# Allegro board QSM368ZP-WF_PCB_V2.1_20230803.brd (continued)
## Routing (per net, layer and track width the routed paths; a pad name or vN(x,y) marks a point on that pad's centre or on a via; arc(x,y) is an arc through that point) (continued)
HDMITX_SCL_M: length 9.3
  TOP w0.1: v1(7.2,12.43) J0401.15
  BOTTOM w0.1: U0413.3 10.18,15.8 9.53,15.15 8.2,15.15 7.2,14.15 v1(7.2,12.43)
HDMITX_SDA: length 170.4
  TOP w0.1: v1(12.45,6.92) 12.65,6.72 25.95,6.72 26.23,6.45 28.1,6.45 29.7,4.85 29.7,4.38 30.02,4.05 v1(30.82,4.05) ; U1301.385 v1(67.5,66.67)
  INNER LAYER 2 w0.1: v1(91.34,33.74) 91.5,33.58 91.5,32.65 91.45,32.6 91.45,25.88 91.1,25.52 v1(90.45,25.52)
  INNER LAYER 3 w0.1: v1(8.22,21.05) 8.22,20.02 9.15,19.1 11.2,19.1 11.7,18.6 11.7,7.67 v1(12.45,6.92) ; v1(67.5,66.67) 67.61,66.67 67.92,66.36 67.92,64.15 72.01,60.07 74.37,60.07 77.95,56.49 77.95,47 91.21,33.74 v1(91.34,33.74) ; v1(90.45,25.52) 89.88,25.52 81.58,17.23 81.58,5.26 80.17,3.85 60,3.85 57.7,1.55 42.15,1.55 39.9,3.8 31.07,3.8 v1(30.82,4.05)
  BOTTOM w0.1: U0405.2 7.61,20.62 7.6,20.62 R0417.1 v1(8.22,21.05)
HDMITX_SDA_M: length 7.4
  TOP w0.1: J0401.16 6.7,12.32 v1(6.6,12.43)
  BOTTOM w0.1: v1(6.6,12.43) 6.7,12.53 6.7,15.7 6.65,15.75 D0406.1 R0420.1 U0405.3
HP_SNS: length 65.6
  TOP w0.25: U1301.101 v1(29.35,70.58) ; R1018.1 v1(23.57,15.22)
  INNER LAYER 3 w0.25: v1(23.57,15.22) 23.57,15.6 23.15,16.02 23.15,32.17 24.05,33.08 24.05,41.88 21.05,44.88 21.05,48.25 22.6,49.8 26.23,49.8 28.4,51.97 28.4,69.62 v1(29.35,70.58)
HPL_OUT: length 95
  TOP w0.25: v1(29.05,13.02) 29.79,12.28 29.79,10.61 29.77,10.6 R1023.1 ; v1(12.72,74.85) 12.72,75.03 13.5,75.8 28.12,75.8 30.15,73.78 U1301.100 30.15,72.58 v1(30,72.42)
  INNER LAYER 3 w0.25: v1(29.05,13.02) 28.89,13.02 23.52,18.38 23.52,32.02 24.45,32.95 24.45,41.98 21.4,45.03 21.4,48.08 22.77,49.45 26.38,49.45 28.75,51.82 28.75,69.3 30.15,70.7 30.15,72.28 v1(30,72.42)
  BOTTOM w0.25: v1(12.72,74.85) 12.35,74.47 R1004.2 C1017.1
HPR_OUT: length 84.8
  TOP w0.25: v1(28.55,72.42) U1301.102 28.55,74.4 27.73,75.22 13.93,75.22 v1(13.57,74.88) ; v1(22.76,15.69) 21.77,14.7 R1010.1
  INNER LAYER 3 w0.25: v1(28.55,72.42) 28.55,71.9 28.02,71.38 28.02,52.12 26.08,50.17 22.45,50.17 20.68,48.4 20.68,44.73 23.65,41.75 23.65,33.17 22.77,32.3 22.77,15.7 v1(22.76,15.69)
  BOTTOM w0.25: 14.22,74.28 14.22,75.12 13.82,75.12 v1(13.57,74.88)
I2C1_SCL_TP: length 141.2
  TOP w0.1: v1(53.17,92.17) 53.17,92.03 52.73,91.58 48.1,91.58 47.4,90.88 44.8,90.88 v1(44.27,90.35) 43.24,90.35 42.35,91.24 42.35,91.25 41.05,92.55 R0517.1 39.83,92.97 39.77,93.03 D0504.2 39.77,94.22 40.6,95.05 J0503.2 ; J1201.17 114.62,84.8 113.17,83.35 111.1,83.35 110.95,83.2 102.78,83.2 100.21,85.78 96,85.78 95.85,85.62 95.85,85.38 v1(95.42,84.95) ; U1301.45 v1(47.75,66.53)
  INNER LAYER 3 w0.1: v1(95.42,84.95) 94.6,84.12 79.85,84.12 78.1,82.38 74.3,82.38 70.47,86.2 70.47,95.03 67.98,97.53 54.88,97.53 53.73,96.38 53.73,93.12 53.17,92.58 v1(53.17,92.17) ; v1(44.27,90.35) 44.85,90.35 45,90.2 45,89.35 47.6,86.75 47.6,76.85 49.85,74.6 54.5,74.6 57.6,71.5 57.6,68.37 56.5,67.28 49.42,67.28 48.67,66.53 v1(47.75,66.53)
I2C1_SDA_TP: length 145.8
  TOP w0.1: v1(54.7,95.75) 54.7,95.12 55.23,94.6 55.23,93.47 55.15,93.4 55.15,93 54.73,92.58 54.35,92.58 54.15,92.38 54.15,92.15 54.02,92.03 54.02,90.85 52.9,89.72 45.6,89.72 v1(45.4,89.53) 45.25,89.38 43.12,89.38 42,90.5 39.3,90.5 38.45,91.35 38.45,92.3 38.7,92.55 R0508.1 38.98,93.05 39.08,93.15 D0509.2 39.08,93.95 40.1,94.97 J0503.1 ; J1201.19 114.3,87.25 109.62,87.25 109.2,87.67 94.22,87.67 94,87.45 94,83.15 v1(93.5,82.65) ; v1(49.35,66.53) U1301.40
  INNER LAYER 3 w0.1: v1(93.5,82.65) 93.25,82.4 89.08,82.4 88.05,83.42 80.14,83.42 78.39,81.67 73.95,81.67 69.67,85.95 69.67,94.78 67.65,96.8 65.15,96.8 64.5,96.15 63.73,96.15 63.08,96.8 56.05,96.8 55,95.75 v1(54.7,95.75) ; v1(49.35,66.53) 49.35,66.9 49.52,67.08 56.6,67.08 57.8,68.28 57.8,71.6 54.6,74.8 49.95,74.8 47.8,76.95 47.8,86.85 45.4,89.25 v1(45.4,89.53)
I2C2_SCL_M1: length 104.4
  TOP w0.1: J0201.13 93.85,97 v1(93.95,96.9) ; U1301.287 58.95,37.17 58.55,37.58 v1(58.55,37.73) ; v1(96.7,80.45) 96.2,79.95 96.2,71.87 95.42,71.1 95.42,63.88 82.6,51.05 74.35,51.05 73.85,50.55 73.15,50.55 72.95,50.35 v1(72.95,50.02)
  INNER LAYER 3 w0.1: v1(72.95,50.02) 72.78,49.85 72.08,49.85 71.28,49.05 70.42,49.05 69.78,48.4 65.42,48.4 63.06,46.04 63.06,44.64 58.6,40.17 58.6,37.77 v1(58.55,37.73) ; v1(93.95,96.9) 93.95,96.45 93.62,96.12 90.28,96.12 89.95,95.8 89.95,95.22 91.35,93.83 92.97,93.83 94.97,91.83 94.97,90.8 98.78,87 98.78,82.18 96.94,80.34 96.8,80.34 v1(96.7,80.45)
  BOTTOM w0.1: v1(93.95,96.9) 94.17,96.9 94.53,96.55 94.53,95.1 93.92,94.5 89.62,94.5 89.42,94.7 88.25,94.7 88.12,94.83 R0207.1
I2C2_SDA_M1: length 101.3
  TOP w0.1: v1(94.12,96.05) 94.15,96.03 J0201.12 ; U1301.284 58.15,38.75 57.62,39.27 v1(57.62,39.45) ; v1(73.58,50.15) 73.75,50.15 74.45,50.85 82.7,50.85 95.62,63.77 95.62,70.92 96.42,71.72 96.42,79.55 v1(96.69,79.81)
  INNER LAYER 3 w0.1: v1(73.58,50.15) 73.47,50.15 72.65,50.98 71.75,50.98 71.38,50.6 71.38,50.27 70.75,49.65 70.12,49.65 69.47,49 65.08,49 62.42,46.35 62.42,44.85 57.88,40.3 57.88,39.7 v1(57.62,39.45) ; v1(94.12,96.05) 94,95.92 90.38,95.92 90.15,95.7 90.15,95.33 91.45,94.03 93.15,94.03 95.25,91.92 95.25,90.83 98.97,87.1 98.97,82.05 96.92,80 96.87,80 v1(96.69,79.81)
  BOTTOM w0.1: v1(94.12,96.05) 94.33,95.85 94.33,95.2 93.83,94.7 89.72,94.7 89.3,95.12 R0221.1
I2C3_SCL_M0: length 122.8
  TOP w0.1: J0202.13 83.17,97.15 v1(83.72,96.6) ; U1301.273 v1(54.15,37.55) ; v1(72.53,50.48) 72.83,50.77 73.78,50.77 74.25,51.25 82.5,51.25 95.2,63.95 95.2,71.28 95.9,71.97 95.9,81.97 97.15,83.22 97.15,84.25 v1(97.4,84.5) 97.53,84.62 99.58,84.62 103.47,80.72 109.53,80.72 110.47,81.67 113.88,81.67 J1201.13
  INNER LAYER 3 w0.1: v1(97.4,84.5) 96.47,85.42 96.47,87.45 89.58,94.35 85.45,94.35 84.25,95.55 83.83,95.55 83.7,95.67 83.7,96.58 v1(83.72,96.6) ; v1(72.53,50.48) 72.15,50.1 71.97,50.1 71.12,49.25 70.33,49.25 69.67,48.6 65.3,48.6 62.85,46.15 62.85,44.71 58.4,40.26 58.4,39.27 57.6,38.48 54.85,38.48 54.15,37.77 v1(54.15,37.55)
  BOTTOM w0.1: v1(83.72,96.6) 83.72,97.38 84.33,97.97 87.65,97.97 87.85,97.78 R0208.1
I2C3_SDA_M0: length 129.8
  TOP w0.1: U1301.268 v1(52.55,37.48) ; J1201.11 115.62,79.92 115.62,81.28 115.03,81.88 110.39,81.88 109.44,80.92 103.56,80.92 99.58,84.9 96.9,84.9 96.72,84.72 v1(96.72,84.58) 96.92,84.38 96.92,83.43 95.67,82.18 95.67,72.12 95,71.45 95,64.05 82.42,51.48 74.18,51.48 73.7,51 72.38,51 v1(71.9,50.52) ; J0202.12 83.47,95.33 83.3,95.5 v1(83.3,96)
  INNER LAYER 3 w0.1: v1(71.9,50.52) 71.9,50.48 70.88,49.45 70.22,49.45 69.58,48.8 65.2,48.8 62.63,46.23 62.63,44.77 58.2,40.34 58.2,39.38 57.51,38.69 54.71,38.69 53.5,37.48 v1(52.55,37.48) ; v1(83.3,96) 83.3,95.78 83.72,95.35 84.15,95.35 85.35,94.15 89.47,94.15 96.28,87.35 96.28,85.33 96.72,84.88 v1(96.72,84.58)
  BOTTOM w0.1: v1(83.3,96) 83.33,96.03 83.33,97.28 84.25,98.2 88.85,98.2 88.97,98.08 R0222.1
I2C4_SCL_M1: length 141.8
  TOP w0.1: U1301.159 v1(30.52,49.88) ; v1(36.75,98.55) 36.75,97.47 37.8,96.42 v1(37.8,90.85) ; v1(90.2,86.85) 90,86.65 90,84.95 91,83.95 91,75.97 87.38,72.35 v1(87.38,71.97)
  INNER LAYER 3 w0.1: v1(30.52,49.88) 30.52,50.1 31.02,50.6 31.02,56 31.57,56.55 31.57,69.77 33.33,71.53 36.4,71.53 39.52,74.65 39.52,87.3 37.8,89.03 v1(37.8,90.85) ; v1(90.2,86.85) 90.1,86.95 85.78,86.95 83.05,89.67 72.3,89.67 71.72,90.25 71.72,95.38 68.47,98.62 53.42,98.62 53.15,98.35 v1(53,98.35) 52.48,98.35 51.95,97.83 48.02,97.83 47.6,97.4 45.48,97.4 45.05,97.83 42.48,97.83 42.17,98.12 37.17,98.12 v1(36.75,98.55)
  BOTTOM w0.1: v1(87.38,71.97) 87.17,71.78 R1206.1 87.03,71.38 86.55,70.9 U1204.2 ; v1(53,98.35) 53,97.05 52.73,96.78 R0430.2 52.73,94.03 U0410.2
I2C4_SDA_M1: length 143.8
  TOP w0.1: v1(38.2,90.4) 38.2,91.05 38.02,91.22 38.02,96.5 36.95,97.58 36.95,98.08 v1(37.4,98.53) ; v1(90.83,86.88) 90.25,86.3 90.25,85 91.22,84.03 91.22,75.85 88.3,72.92 88.3,71 v1(87.17,69.88) ; U1301.155 v1(31.55,51.4)
  INNER LAYER 3 w0.1: v1(31.55,51.4) 31.23,51.73 31.23,55.88 31.8,56.45 31.8,69.67 33.42,71.3 36.48,71.3 39.73,74.55 39.73,87.4 38.2,88.92 v1(38.2,90.4) ; v1(37.4,98.53) 37.6,98.33 42.27,98.33 42.58,98.03 45.15,98.03 45.58,97.6 47.5,97.6 47.92,98.03 51.58,98.03 v1(51.8,98.25) 52.08,98.25 52.38,98.55 52.62,98.55 52.92,98.85 68.55,98.85 71.92,95.48 71.92,90.35 72.4,89.88 83.14,89.88 85.76,87.25 90.45,87.25 v1(90.83,86.88)
  BOTTOM w0.1: U1204.3 86.6,70.2 86.92,70.53 R1203.1 v1(87.17,69.88) ; v1(51.8,98.25) 51.55,98.5 R0424.2 50.95,97.35 51.12,97.17 51.12,96.75 49.5,95.12 U0407.2
I2S3_LRCKM1: length 77.8
  TOP w0.1: U1301.388 69,69.08 70.55,70.62 77.2,70.62 v1(78.1,69.72) ; v1(94.12,32.17) 94.22,32.17 97.1,29.3 106.12,29.3 106.62,28.8 106.62,25.27 106.15,24.8 105.88,24.8 R0714.1
  INNER LAYER 3 w0.1: v1(78.1,69.72) 78.1,69.22 78.53,68.8 78.53,63.6 77.47,62.55 77.47,59.38 79.6,57.25 79.6,47.75 91.15,36.2 92.92,36.2 94.7,34.42 94.7,32.75 v1(94.12,32.17)
I2S3_SCLKM1: length 80.8
  TOP w0.1: U1301.386 69.22,67.47 71.67,69.92 v1(76.58,69.92) ; R0724.1 103.17,24.57 103.28,24.48 104.15,24.48 104.53,24.1 106.53,24.1 107.28,24.85 107.28,29.12 106.5,29.9 97.72,29.9 94.05,33.58 94.05,33.8 v1(94.03,33.83)
  INNER LAYER 3 w0.1: v1(94.03,33.83) 94.03,34.38 92.6,35.8 90.95,35.8 79.17,47.58 79.17,57.08 77.05,59.2 77.05,62.8 77.94,63.69 77.94,68.56 v1(76.58,69.92)
I2S3_SDIM1: length 79.7
  TOP w0.1: U1301.383 68.92,65.88 69.25,66.2 69.25,67.15 71.83,69.72 75.17,69.72 v1(76.25,68.65) ; R0703.1 104.03,24.9 104.62,24.3 106.4,24.3 107.03,24.93 107.03,29.05 106.38,29.7 97.55,29.7 93.83,33.42 v1(93.33,33.42)
  INNER LAYER 3 w0.1: v1(93.33,33.42) 93.17,33.42 92.88,33.73 92.88,34.58 92.12,35.33 90.83,35.33 78.75,47.4 78.75,56.9 76.12,59.52 76.12,63.42 77.28,64.58 77.28,67.62 v1(76.25,68.65)
I2S3_SDOM1: length 67.8
  TOP w0.1: R0710.1 104.88,24.8 105.17,24.5 106.28,24.5 106.83,25.05 106.83,28.93 106.25,29.5 97.38,29.5 93.92,32.95 v1(93.72,32.95) ; v1(69.28,64.28) U1301.380
  INNER LAYER 3 w0.1: v1(93.72,32.95) 93.15,32.95 92.62,33.48 92.62,34.52 92.03,35.12 90.72,35.12 78.55,47.3 78.55,56.77 74.55,60.77 72.33,60.77 69.28,63.83 v1(69.28,64.28)
INTB_A: length 9.5
  BOTTOM w0.1: R0953.2 111.72,50.8 R0935.2 D0902.1 111.25,48.6 110.62,47.98 109.38,47.98 109.03,47.62 109.03,46.73 107.62,45.33 U0902.31
LAN0_D2_REC1_A: length 1.6
  BOTTOM w0.3: R0911.2 98.92,24.23 U0901.24
LAN0_D2_REC2_A: length 1.6
  BOTTOM w0.3: U0901.21 101.92,24.27 R0918.2
LAN0_D7_REC1_A: length 1.6
  BOTTOM w0.3: U0901.15 107.92,24.25 R0924.2
LAN0_D7_REC2_A: length 1.6
  BOTTOM w0.3: R0943.2 104.92,24.29 U0901.18
LCD0_BL_PWM4: length 80.3
  TOP w0.1: U0409.5 R0422.2 v1(69.28,89.62) ; v1(48.15,88.05) 49.62,89.53 53,89.53 54.23,90.75 54.23,91.85 v1(54.55,92.17) ; U1301.55 v1(44.55,66.55)
  INNER LAYER 3 w0.1: v1(54.55,92.17) 54.55,92.58 54.85,92.88 54.85,93.62 54.42,94.05 54.42,94.85 56.17,96.6 62.98,96.6 63.62,95.95 64.6,95.95 65.25,96.6 67.55,96.6 69.47,94.67 69.47,89.83 v1(69.28,89.62) ; v1(48.15,88.05) 48.4,87.8 48.4,77.2 50.2,75.4 54.85,75.4 58.4,71.85 58.4,68.03 56.85,66.47 54.52,66.47 52.35,64.3 46.45,64.3 44.55,66.2 v1(44.55,66.55)
LCD1_BL_PWM5: length 14
  TOP w0.1: U1301.25 v1(54.15,64.72)
  INNER LAYER 2 w0.1: v1(54.15,64.72) 55.27,65.85 57.77,65.85 59.73,67.8 62.38,67.8 v1(63.58,69)
  BOTTOM w0.1: U0504.5 62.58,69.22 R0512.2 v1(63.58,69)
LCD_RST_L_GPIO3_C7: length 146.1
  TOP w0.1: U1301.322 67.42,46.05 67.42,46.65 67.53,46.75 68.88,46.75 69.25,47.12 69.25,47.82 70.6,49.17 83.78,49.17 90.09,55.49 90.09,57.94 95.83,63.67 95.83,70.75 97.4,72.33 97.4,81.15 v1(97.08,81.47) ; v1(29.48,98.53) J0501.6 ; v1(54.15,93.28) 53.98,93.1 53.4,93.1 52.98,93.53 52.67,93.53 51.65,92.5 45.4,92.5 v1(45.2,92.7)
  INNER LAYER 3 w0.1: v1(29.48,98.53) 29.75,98.53 30.35,97.92 30.57,97.92 30.98,97.53 34.98,97.53 35.95,96.55 40.88,96.55 44.52,92.9 45,92.9 v1(45.2,92.7) ; v1(97.08,81.47) 96.78,81.78 95.88,81.78 93.72,83.92 79.93,83.92 78.18,82.17 74.2,82.17 70.25,86.12 70.25,94.95 67.9,97.3 54.95,97.3 53.92,96.28 53.92,93.5 v1(54.15,93.28)
LCDC_D0: length 61.1
  TOP w0.1: U1301.366 68.65,58.67 71.9,61.92 74.9,61.92 79.67,66.7 83.5,66.7 85.76,68.96 88.76,68.96 92.18,72.38 92.18,84.25 92.3,84.38 92.3,85.9 v1(92.15,86.05)
  INNER LAYER 3 w0.1: v1(79.5,88.75) 80.2,88.75 83.6,85.35 91.03,85.35 91.72,86.05 v1(92.15,86.05)
  BOTTOM w0.1: v1(79.5,88.75) 79.6,88.65 79.6,87.75 80.15,87.2 R0203.2 80.62,88.2 U0202.3
LCDC_D1: length 143.7
  TOP w0.1: R0507.2 15.15,95.58 15.47,95.25 18.43,95.25 18.73,94.95 v1(19,94.95) ; R0507.2 R0504.1 ; R0507.2 U0502.3 ; v1(91.9,84.97) 91.9,84.4 91.96,84.34 91.96,72.46 88.67,69.17 85.67,69.17 83.4,66.9 79.58,66.9 74.8,62.12 71.8,62.12 69.15,59.48 U1301.367 ; v1(52.05,93.5) 52.05,93.2 51.55,92.7 45.98,92.7 v1(45.77,92.9)
  INNER LAYER 3 w0.1: v1(52.05,93.5) 52.95,93.5 53.12,93.67 53.12,96.67 54.58,98.12 68.22,98.12 71.15,95.2 71.15,86.4 74.58,82.97 77.85,82.97 79.6,84.72 91.72,84.72 91.9,84.9 v1(91.9,84.97) ; v1(19,94.95) 19.57,94.95 21.16,96.54 26.31,96.54 28.7,98.92 29.65,98.92 30.45,98.12 30.68,98.12 31.07,97.72 35.08,97.72 36.05,96.75 40.98,96.75 44.62,93.1 45.58,93.1 v1(45.77,92.9)
LCDC_D9: length 59.4
  TOP w0.1: v1(92.55,87.6) 92.55,84.23 92.39,84.06 92.39,72.29 88.85,68.75 85.85,68.75 83.58,66.47 79.78,66.47 75,61.7 72.97,61.7 68.95,57.67 67.67,57.67 67,57 65.72,57 65.53,57.2 65.53,57.65 65.3,57.88 U1301.359
  INNER LAYER 3 w0.1: v1(88.17,88.53) 88.5,88.2 91.95,88.2 v1(92.55,87.6)
  BOTTOM w0.1: v1(88.17,88.53) R0204.2 87.55,89.6 87.2,89.95 U0204.5
LCDC_D10: length 71.8
  TOP w0.1: U1301.354 65.15,56.27 65.75,55.67 67.03,55.67 67.42,56.08 69.2,56.08 69.5,56.38 69.5,57.33 73.28,61.1 75.33,61.1 80.08,65.85 83.92,65.85 86.19,68.11 89.11,68.11 93.02,72.02 93.02,83.7 93.17,83.85 93.17,85.55 93.35,85.72 v1(93.35,85.83)
  INNER LAYER 3 w0.1: v1(93.35,85.83) 93.35,85.75 93.25,85.65 91.67,85.65 91.15,85.12 77.65,85.12 v1(76.25,86.53)
  BOTTOM w0.1: v1(76.25,86.53) 76.58,86.85 R0223.2 U0203.3
LCDC_D12: length 78.1
  TOP w0.1: v1(95.12,86.75) 94.47,86.1 94.47,81.58 93.29,80.39 93.29,71.14 89.72,67.58 89.72,66.4 89.28,65.95 85.55,65.95 82.4,62.8 80.4,62.8 77.62,60.02 74.67,60.02 68.53,53.88 U1301.351
  INNER LAYER 3 w0.1: v1(72.1,87.15) 72.1,85.78 74.7,83.17 77.77,83.17 79.52,84.92 91.25,84.92 91.72,85.4 93.78,85.4 v1(95.12,86.75)
  BOTTOM w0.1: U0205.3 R0228.1 v1(72.1,87.15)
LCDC_D13: length 138.3
  TOP w0.1: v1(67.5,52.42) 67.65,52.27 U1301.346 ; v1(20.7,16.55) R1017.1 C1024.2 R1014.1
  INNER LAYER 2 w0.1: v1(88.72,32.48) v1(88.72,27.43)
  INNER LAYER 3 w0.1: v1(88.72,27.43) 88.72,26.75 79.95,17.98 79.95,8.28 78.33,6.65 58.62,6.65 56.4,4.42 43.3,4.42 41.08,6.65 33.35,6.65 29.57,10.43 29.57,11.18 26.43,14.32 22.55,14.32 20.7,16.18 v1(20.7,16.55) ; v1(88.72,32.48) 88.55,32.65 88.55,33.98 76.6,45.92 76.6,55.9 75.92,56.58 71.65,56.58 71.22,56.15 69.25,56.15 67.75,54.65 67.75,52.67 v1(67.5,52.42)
LCDC_D15: length 73.2
  TOP w0.1: v1(95.85,38.4) 95.95,38.3 96.8,38.3 98.22,39.73 102.33,39.73 103.63,38.42 110.6,38.42 v1(110.92,38.75) ; U1301.348 65.28,53.88 65.44,54.04 65.44,54.89 65.78,55.23 67.03,55.23 67.38,54.88 68.94,54.88 74.52,60.45 77.35,60.45 80.35,63.45 v1(80.62,63.45)
  INNER LAYER 3 w0.1: v1(95.85,38.4) 95.62,38.17 91.62,38.17 84.47,45.33 84.47,46.1 82.12,48.45 82.12,58 81.25,58.88 81.25,62.83 v1(80.62,63.45)
  BOTTOM w0.1: v1(110.92,38.75) 110.95,38.77 111.47,38.77 111.67,38.58 111.67,38.62 111.7,38.65 D0905.1
LCDC_D19: length 289.1
  TOP w0.1: v1(98.1,56.2) 98.45,56.2 98.67,56.42 107.92,56.42 112.82,51.52 113.25,51.52 114.92,49.85 v1(116.53,49.85) ; U1301.342 67,51.48 67.22,51.25 69.42,51.25 69.58,51.4 69.58,52.67 70.03,53.12 70.03,53.85 75.2,59.02 81.15,59.02 81.92,59.8 v1(81.92,60.17) ; v1(29.45,3.4) 28.77,4.08 28.77,5.15 27.93,6 26.07,6 25.75,6.33 12.38,6.33 12.18,6.12 v1(11.55,6.12)
  INNER LAYER 3 w0.1: v1(98.1,56.2) 97.95,56.2 97.72,55.98 93.4,55.98 92.97,56.4 84.65,56.4 81.92,59.12 v1(81.92,60.17) ; v1(4.1,70.45) 2.75,70.45 1.3,69 1.3,43.38 5.62,39.05 5.62,30.82 5.88,30.57 5.88,27.3 4.6,26.02 3.35,26.02 1.32,24 1.32,14.93 2.04,14.21 2.34,14.21 2.85,13.7 2.85,13.4 4.53,11.72 4.53,10.55 8.95,6.12 v1(11.55,6.12) ; v1(116.53,49.85) 116.35,49.67 116.35,48.05 116.74,47.66 116.74,44.66 116.22,44.15 116.22,31.75 111.9,27.43 100.15,27.43 98.28,25.55 98.28,14.97 86.75,3.45 60.17,3.45 57.88,1.15 41.95,1.15 39.7,3.4 v1(29.45,3.4)
  BOTTOM w0.1: v1(4.1,70.45) R1022.1 R1015.2 10.3,70.45 10.4,70.35 U1001.9
LCDC_D21: length 88.3
  TOP w0.1: v1(93.7,80.1) 93.55,79.95 93.55,70.97 90.78,68.2 90.78,66.55 89.75,65.53 85.85,65.53 83.62,63.3 83.62,61.17 81.28,58.83 75.3,58.83 70.22,53.75 70.22,53.02 69.78,52.58 69.78,50.48 69.17,49.88 U1301.337 ; v1(67.28,85.65) 67.28,85.78 66.3,86.75 66.3,89.7 67.22,90.62 67.22,91.85 67.8,92.42 v1(67.8,92.7)
  INNER LAYER 3 w0.1: v1(93.7,80.1) 73.35,80.1 68.12,85.33 67.6,85.33 v1(67.28,85.65)
  BOTTOM w0.1: 66.2,94.08 R0406.2 67.17,93.33 v1(67.8,92.7)
LCDC_HSYNC: length 90.9
  TOP w0.1: v1(44.05,31.75) 44.05,31.2 48.4,26.85 53.17,26.85 55.38,24.65 v1(55.6,24.65) ; v1(56.7,41.8) 56.7,44.52 v1(57.21,45.04) ; U1301.333 v1(61.73,49.08)
  INNER LAYER 3 w0.1: v1(56.7,41.8) 56.12,41.23 52.08,41.23 51.67,40.83 51.67,36.83 51.23,36.38 48.3,36.38 46.73,34.8 42.85,34.8 42.38,34.33 42.38,33.42 v1(44.05,31.75)
  BOTTOM w0.1: v1(57.21,45.04) 57.21,45.14 61.15,49.08 v1(61.73,49.08) ; R0319.1 30.18,20.62 30.07,20.52 30.07,15.25 32.45,12.88 35.62,12.88 37.15,14.4 37.15,15.45 38.8,17.1 40.45,17.1 42.77,19.43 42.77,21.85 44.92,24 54.95,24 v1(55.6,24.65)
LCM_LED+: length 58.3
  TOP w0.2: v1(31.5,98.53) 31.48,98.5 J0501.1
  INNER LAYER 3 w0.2: v1(69.5,72.6) 67.35,74.75 63.15,74.75 61.95,75.95 50.5,75.95 48.95,77.5 48.95,88.47 46.55,90.88 46.55,93.3 46.17,93.67 44.85,93.67 41.2,97.33 36.27,97.33 35.33,98.28 31.75,98.28 v1(31.5,98.53)
  BOTTOM w0.2: v1(69.5,72.6) R0523.1
LCM_LED-: length 51.9
  TOP w0.2: J0501.3 v1(30.68,98.53)
  INNER LAYER 3 w0.2: v1(30.68,98.53) 31.23,97.97 35.2,97.97 36.17,97 41.1,97 44.72,93.38 46.05,93.38 46.25,93.17 46.25,90.75 48.65,88.35 48.65,77.35 50.35,75.65 57.15,75.65 v1(57.42,75.38)
  BOTTOM w0.2: v1(57.42,75.38) 60.55,75.38 61.92,74 R0530.2 61.92,71.97
LCMIO_1V8: length 13.8
  TOP w0.23: v1(26.77,98.53) 26.68,98.42 J0501.13
  TOP w0.3: R0513.1 v1(17.82,93.58)
  BOTTOM w0.3: v1(26.77,98.53) R0511.2 C0519.2 26.15,97.33 25.85,97.03 19.98,97.03 17.82,94.88 v1(17.82,93.58)
LED0/PHYAD0_A: length 7.3
  BOTTOM w0.1: U0902.32 107.53,44.92 109.22,46.62 109.22,47.52 109.47,47.77 110.75,47.77 111.22,48.25 111.83,48.25 R0956.2
LED1/CFG_LDO0_A: length 46.7
  TOP w0.1: v1(114.58,48.65) 117.25,48.65 117.85,48.05 117.85,35.98 v1(117.17,35.3) ; R0939.1 R0933.1 v1(111.28,18.9)
  INNER LAYER 3 w0.1: v1(111.28,18.9) 111.78,19.4 111.78,24.9 117.08,30.2 117.08,35.2 v1(117.17,35.3)
  BOTTOM w0.1: v1(114.58,48.65) R0907.2 113.38,48.05 111.35,48.05 110.88,47.58 109.58,47.58 109.42,47.42 109.42,46.53 107.42,44.52 U0902.33
LED2/CFG_LDO1_A: length 44.8
  TOP w0.1: v1(112.28,32.08) 113.1,31.25 113.1,26.2 111.38,24.48 109.47,24.48 107.22,22.23 105.38,22.23 105.05,21.9 105.05,20.98 104.22,20.15 104.22,19.38 R0930.1 104.45,19.15 R0951.1
  INNER LAYER 3 w0.1: v1(114.45,46.83) 114.28,46.65 114.28,33.65 112.7,32.08 v1(112.28,32.08)
  BOTTOM w0.1: U0902.34 107.33,44.12 109.12,45.92 109.75,45.92 R0914.1 110.4,46.58 110.75,46.58 111.35,47.17 114.17,47.17 114.45,46.9 v1(114.45,46.83)
LVDS_CTP28: length 42.4
  TOP w0.1: J0402.5 v1(47.85,96.33)
  INNER LAYER 3 w0.2: v1(55.4,92.4) 55.1,92.7 55.1,93.85 55.27,94.03 55.27,94.9 56.4,96.03 62.73,96.03 63.35,95.4 64.85,95.4 65.5,96.05 67.28,96.05 68.92,94.4 68.92,92.55 67.95,91.58 v1(64.92,91.58)
  BOTTOM w0.2: R0415.2 48.3,96.78 v1(47.85,96.33) 47.75,96.22 R0429.2 C0403.1 47.8,93.25 R0404.2 R0414.2 49.08,93.62 49.7,93.62 49.9,93.42 49.9,92.72 51.33,91.3 54.7,91.3 55.4,92 v1(55.4,92.4) ; B0501.2 v1(64.92,91.58)
LVDS_LEDA: length 5.1
  TOP w0.3: R0402.1 74.85,93.97 J0403.40 74.85,96.15 74.35,96.65 J0403.39
LVDS_LEDK: length 16.3
  TOP w0.3: J0403.31 70.35,96.65 70.85,96.15 J0403.32 70.85,94.38 69.12,92.65 68.47,92.65 67.53,91.7 67.53,90.5 66.65,89.62 66.65,86.92 67.3,86.28 R0413.2 68.92,86.28 69.38,86.72 69.55,86.72
LVDS_RESET: length 15
  TOP w0.1: J0403.5 57.35,94.42 56.92,94 v1(56.67,94)
  BOTTOM w0.1: R0406.1 67.17,95 67.05,95.12 Q0403.3 R0421.1 C0404.1 58.05,95.12 56.92,94 v1(56.67,94)
LVDS_TP_INT: length 7.1
  TOP w0.1: J0402.3 48.85,93.78 v1(49.45,93.17)
  BOTTOM w0.1: v1(49.45,93.17) 49.45,92.78 49.02,92.35 R0404.1 R0409.1 47.75,92.08 48.48,91.35 Q0405.3
LVDS_TP_RST: length 6
  TOP w0.1: v1(46.92,98.65) 47.15,98.65 47.35,98.45 47.35,97.58
  BOTTOM w0.1: R0429.1 C0406.1 R0418.1 Q0404.3 46.85,98.58 v1(46.92,98.65)
LVDS_TP_SCL: length 8
  TOP w0.1: v1(50.15,93.97) 49.85,94.28 J0402.1
  BOTTOM w0.1: R0430.1 51.42,94.55 51.42,92.88 51.77,92.53 U0410.3 51.23,92.12 50.15,93.21 v1(50.15,93.97) 49.62,93.97 R0414.1
LVDS_TP_SDA: length 5.2
  TOP w0.2: 49.35,97.58 49.35,96.7 49.55,96.5 49.95,96.5 v1(50.35,96.9)
  BOTTOM w0.2: R0415.1 R0424.1 50.05,97.83 49.77,97.55 U0407.3 50.23,97.03 v1(50.35,96.9)
LVDS_VDD3V3: length 12.8
  TOP w0.25: J0403.3 56.35,96.65 55.85,96.15 J0403.2
  TOP w0.4: J0403.2 55.85,94.22
  TOP w0.5: 55.85,94.22 v1(55.85,93.62)
  BOTTOM w0.5: v1(55.85,93.62) 56.28,93.19 57.02,93.19 58.05,94.22 R0421.2 61.73,94.22 61.75,94.2 62.17,94.2 C0407.1 62.62,93.7 62.62,92.75 62.6,92.72
MIC1_INN: length 38.7
  TOP w0.25: R1099.2 18.75,89.55 19.05,89.85 v1(34.8,89.85) ; U1301.97 v1(32.45,73.28)
  INNER LAYER 3 w0.25: v1(32.45,73.28) 33.05,73.88 35.6,73.88 37.76,76.04 37.76,86.54 34.8,89.5 v1(34.8,89.85)
MIC1_INP: length 43.5
  TOP w0.25: v1(34.73,90.45) 34.48,90.2 18.8,90.2 18.35,90.65 C1010.2 17.48,91.05 ; U1301.98 v1(30.95,72.22)
  INNER LAYER 3 w0.25: v1(30.95,72.22) 32.1,72.22 33.38,73.5 35.73,73.5 38.11,75.89 38.11,86.7 35.27,89.54 35.27,90.05 34.88,90.45 v1(34.73,90.45)
MINI-PCIE-C_DTR: length 53.6
  TOP w0.1: R0715.2 v1(112.33,35.27) ; v1(92.85,57.77) 92.85,57.9 92.95,58 96.63,58 97.54,57.08 108.19,57.08 112.67,52.6 v1(113.4,52.6)
  INNER LAYER 3 w0.1: v1(85.1,61.83) 85.22,61.95 90.22,61.95 93,59.17 93,57.92 v1(92.85,57.77) ; v1(113.4,52.6) 113.4,51.4 114,50.8 114,36.95 v1(112.33,35.27)
  BOTTOM w0.1: R0709.2 v1(85.1,61.83)
MINI-PCIE-C_RESET: length 83.2
  TOP w0.1: v1(93.3,57.35) 93.3,57.62 93.47,57.8 96.53,57.8 97.49,56.84 108.09,56.84 112.85,52.08 113.35,52.08 114.65,50.77 115.5,50.77 v1(116.3,51.58) ; R0706.1 97.88,23.52 v1(97.88,23.18)
  INNER LAYER 3 w0.1: v1(97.88,23.18) 98.05,23.35 98.05,25.65 100.05,27.65 111.8,27.65 116,31.85 116,44.25 116.51,44.76 116.51,47.57 116.12,47.95 116.12,51.4 v1(116.3,51.58) ; v1(93.3,57.35) 93.28,57.38 93.28,57.52 93.25,57.55 93.25,59.25 90.33,62.17 86.7,62.17 85.62,63.25 v1(85.58,63.25)
  BOTTOM w0.1: R0711.2 v1(85.58,63.25)
MINI-PCIE-C_RXD: length 79.2
  TOP w0.1: v1(115.05,50.3) 114.8,50.3 113.3,51.8 112.82,51.8 108,56.62 97.4,56.62 97.03,57 95.95,57 95.67,56.73 92.05,56.73 v1(91.97,56.8) ; R0701.1 v1(95.35,24.5)
  INNER LAYER 3 w0.1: v1(84.15,57.52) 85.03,56.65 91.83,56.65 v1(91.97,56.8) ; v1(115.05,50.3) 115.25,50.1 115.25,50.08 115.47,49.86 115.47,47.68 115.85,47.3 115.85,45.03 115.34,44.52 115.34,32.12 111.65,28.43 98.38,28.43 95.35,25.4 v1(95.35,24.5)
  BOTTOM w0.1: R0702.2 84.38,57.3 v1(84.15,57.52)
MINI-PCIE-C_TXD: length 77.2
  TOP w0.1: v1(92.4,58.2) 97.83,58.2 98.72,57.3 108.37,57.3 112.67,53 114.05,53 115.22,51.83 v1(115.35,51.83) ; R0732.1 v1(96.17,25.62)
  INNER LAYER 3 w0.1: v1(92.4,58.2) 91.55,59.05 v1(85.15,59.05) ; v1(96.17,25.62) 96.17,25.85 98.53,28.2 111.73,28.2 115.55,32.03 115.55,44.43 116.07,44.94 116.07,47.38 115.68,47.77 115.68,51.5 v1(115.35,51.83)
  BOTTOM w0.1: R0707.2 v1(85.15,59.05)
MINI-PCIE-C_VDD_EXT: length 18.7
  TOP w0.1: R0719.1 v1(84.25,25.65)
  INNER LAYER 3 w0.1: v1(84.25,25.65) 83.28,26.62 81.8,26.62 81.25,26.07 81.25,20.77 79.9,19.43 78.3,19.43 76.12,21.6 75.33,21.6 v1(75.08,21.35)
  BOTTOM w0.1: R0866.1 74.78,21.05 v1(75.08,21.35)
MINI-PCIE_DTR: length 67.7
  TOP w0.1: v1(115.89,52.1) 115.89,52.71 114.9,53.7 112.88,53.7 108.67,57.9 100.47,57.9 97.92,60.45 v1(97.7,60.45) ; R0704.1 v1(96.85,23.07)
  INNER LAYER 3 w0.1: v1(115.89,52.1) 115.89,47.86 116.28,47.47 116.28,44.85 115.77,44.34 115.77,31.94 111.72,27.9 100,27.9 96.85,24.75 v1(96.85,23.07)
  BOTTOM w0.1: R0733.2 v1(97.7,60.45)
MINI-PCIE_LED_WWAN#: length 23.1
  TOP w0.1: J0701.42 102.08,36.67 103.42,38.02 111.9,38.02 112.88,37.05 115.08,37.05 116.3,38.27 116.3,41.02 115.45,41.88 D0706.1
MINI-PCIE_RXD: length 77.1
  TOP w0.1: R0719.2 J0701.11 86.47,28.5 86.88,28.9 87.1,28.9 v1(87.25,29.05) ; v1(97.65,58.75) 98.97,58.75 100.22,57.5 108.47,57.5 112.75,53.23 114.45,53.23 v1(114.85,52.83)
  INNER LAYER 3 w0.1: v1(87.25,29.05) 87.33,29.05 88.55,30.27 95.18,30.27 96.76,31.85 102.82,31.85 105.77,28.9 111.53,28.9 114.92,32.29 114.92,44.69 115.43,45.2 115.43,47.12 115.04,47.51 115.04,49.36 114.42,49.98 114.42,52.4 v1(114.85,52.83)
  BOTTOM w0.1: R0731.2 v1(97.65,58.75)
MINI-PCIE_TXD: length 76
  TOP w0.1: v1(97.72,59.6) 98.47,59.6 100.38,57.7 108.58,57.7 112.8,53.48 114.8,53.48 115.38,52.9 v1(115.38,52.42) ; v1(87.97,29.1) 87.28,28.4 J0701.13
  INNER LAYER 3 w0.1: v1(115.38,52.42) 115.03,52.42 114.64,52.04 114.64,50.09 115.25,49.47 115.25,47.6 115.64,47.21 115.64,45.12 115.13,44.6 115.13,32.2 111.62,28.7 105.65,28.7 102.72,31.62 96.85,31.62 95.28,30.05 88.62,30.05 87.97,29.4 v1(87.97,29.1)
  BOTTOM w0.1: R0729.2 v1(97.72,59.6)
MINI-PCIE_W_DISABLE#: length 27.1
  TOP w0.1: v1(93.25,37.12) 93.28,37.1 J0701.20
  INNER LAYER 3 w0.1: v1(80.75,54.45) 80.35,54.05 80.35,48.12 91.15,37.33 93.05,37.33 v1(93.25,37.12)
  BOTTOM w0.1: v1(80.75,54.45) 81.05,54.75 C0701.2 81.05,55.55 81.1,55.6 D0701.3
MINI-PCIE_W_RESET#: length 41.7
  TOP w0.1: J0701.22 v1(94.08,37.1)
  INNER LAYER 3 w0.1: v1(80.7,64.55) 80.6,64.55 79.9,63.85 79.9,59.5 81.6,57.8 81.6,47.17 91.22,37.55 93.88,37.55 94.08,37.35 v1(94.08,37.1)
  BOTTOM w0.1: v1(80.7,64.55) 85.2,64.55 R0716.2
MIPI_CTP28: length 39.6
  TOP w0.2: J0503.6 42.6,94.95 43.05,94.5 43.5,94.5 44.12,93.88 C0533.1 44.12,92.35 44.45,92.03 51.9,92.03 52.52,92.65 53.35,92.65 53.52,92.83 54.38,92.83 54.88,93.33 54.88,94.17 v1(54.83,94.22)
  INNER LAYER 3 w0.2: v1(66.4,91.12) 66.55,91.28 68.08,91.28 69.22,92.42 69.22,94.55 67.42,96.35 65.38,96.35 64.72,95.7 63.5,95.7 62.88,96.33 56.27,96.33 54.83,94.88 v1(54.83,94.22)
  BOTTOM w0.2: v1(66.4,91.12) 66.22,90.95 B0502.2
MODULE_4G_3V5: length 154.4
  TOP w0.2: R0728.2 94.22,39.15 93.47,38.4 91.8,38.4 90.65,37.25 81.95,37.25 81.2,36.5 v1(81.2,34.17) ; v1(86.15,49.45) 86.15,49.95 92.62,56.42 v1(95.95,56.42)
  TOP w0.3: v1(115.03,46.17) 115.25,46.17 115.55,46.48 R0708.1 R0730.1
  TOP w0.5: J0701.52 106.08,34.55 107.62,33 109.7,33 110.9,31.8 v1(110.9,29.77) 110.9,26.48 110.15,25.73 109.22,25.73 106.9,23.4 101.5,23.4 101.35,23.55
  TOP w0.6: J0701.39 100.88,26.18 101.35,25.7 101.67,26.02 J0701.41
  TOP w1.5: 101.35,25.7 101.35,23.55 99.25,21.45 90.28,21.45 87.67,24.05 79.72,24.05 77.08,26.7 77.08,30.9 80.1,33.92 80.92,33.92
  INNER LAYER 2 w0.1: v1(75.6,30) 74.75,30.85 64.78,30.85 64.25,31.38 v1(64.25,31.57)
  INNER LAYER 3 w0.2: v1(110.9,29.77) 114.58,33.45 114.58,44.75 115.03,45.2 v1(115.03,46.17)
  BOTTOM w0.1: L0701.2 77.65,30.93 77.62,30.9 76.95,30.9 76.92,30.93 76.92,30.9 76.03,30 v1(75.6,30) ; v1(64.25,31.57) 64.25,32.33 64.9,32.98 R0717.2
  BOTTOM w0.2: U0702.14 95.75,58.1 C0703.1 C0705.1 v1(95.95,56.42)
  BOTTOM w0.3: v1(86.15,49.45) 84.72,48.02 84.72,36.92 84.15,36.35 84.15,35 84.1,35
  vias: v1(81.2,33.52) v1(81.88,34.15) v1(81.9,33.5) v1(82.5,34.17) v1(82.53,33.55) v1(83.12,34.17) v1(83.17,33.52)
PDM_CLK1_M0_ADC: length 95.8
  TOP w0.1: v1(93.72,66.35) 93.72,63.98 82.05,52.3 73.3,52.3 73.2,52.2 v1(73.2,52.1) ; U1301.258 v1(49.35,37.5)
  INNER LAYER 3 w0.1: J1201.14 115.65,79.95 113.17,79.95 111.05,77.83 111.05,70.15 109.67,68.78 106.58,68.78 105.05,70.3 102.08,70.3 97.8,66.03 94.05,66.03 v1(93.72,66.35) ; v1(73.2,52.1) 72.72,51.62 70.78,51.62 68.96,49.81 64.54,49.81 61.5,46.77 61.5,45.17 58.77,42.45 52.05,42.45 49.35,39.75 v1(49.35,37.5)
PDM_SDI1_M0_ADC: length 194.3
  TOP w0.1: v1(95.4,85.58) 95.5,85.58 95.9,85.97 100.36,85.97 102.89,83.45 110.65,83.45 112.03,84.83 112.25,84.83 113.22,85.8 115.12,85.8 115.62,85.3 115.62,83.92 J1201.16 ; v1(47.23,91.28) 47.5,91.28 48,91.78 52.3,91.78 v1(52.58,92.05) ; U1301.253 v1(47.75,37.52) ; v1(71.95,52.38) 72.3,52.38 72.67,52.75 81.83,52.75 92.78,63.7 v1(92.78,66.95)
  INNER LAYER 3 w0.1: v1(47.75,37.52) 47.75,38.73 51.87,42.85 58.61,42.85 61.04,45.28 61.04,47.02 64.25,50.23 68.75,50.23 70.62,52.1 71.67,52.1 v1(71.95,52.38) ; v1(95.4,85.58) 95.25,85.58 94.97,85.3 94.97,84.92 94.38,84.33 79.77,84.33 78.02,82.58 74.4,82.58 70.67,86.3 70.67,95.11 68.06,97.72 54.77,97.72 53.52,96.47 53.52,93.22 52.58,92.28 v1(52.58,92.05) ; J1201.16 115.65,81.95 113.72,81.95 113.03,81.25 113.03,80.4 110.65,78.03 110.65,70.35 109.47,69.17 106.78,69.17 105.22,70.72 101.9,70.72 97.62,66.45 96.12,66.45 95.38,67.2 93.53,67.2 93.28,66.95 v1(92.78,66.95)
  BOTTOM w0.1: v1(47.23,91.28) 46.95,91 46.34,91 45.83,91.53 R0403.1 45.45,91.85 45.77,92.17 46.67,92.17 R0409.2
PDM_SDI2_M0_ADC: length 185.2
  TOP w0.1: v1(71.38,52.62) 71.53,52.77 72.35,52.77 72.55,52.98 81.77,52.98 92.38,63.58 92.38,67.15 92.67,67.45 v1(93.17,67.45) ; v1(94.55,87.2) 94.58,87.2 94.78,87.4 109.1,87.4 109.65,86.85 113.12,86.85 113.97,86 115.33,86 116.4,84.92 J1201.18 ; U1301.248 v1(46.9,36.67)
  INNER LAYER 3 w0.1: J1201.18 115.62,83.92 113.83,83.92 112.83,82.92 112.83,80.53 110.45,78.15 110.45,70.45 109.38,69.38 106.88,69.38 105.33,70.92 101.8,70.92 97.53,66.65 96.22,66.65 95.42,67.45 v1(93.17,67.45) ; v1(46.9,36.67) 47.3,37.08 47.3,37.8 47.55,38.05 47.55,38.82 51.78,43.05 58.53,43.05 60.78,45.3 60.78,47.08 64.12,50.42 68.65,50.42 70.55,52.33 71.08,52.33 v1(71.38,52.62) ; v1(46.35,98.45) 46.35,98.8 46.6,99.05 68.65,99.05 72.12,95.58 72.12,90.45 72.5,90.08 83.22,90.08 85.79,87.5 91.35,87.5 91.92,86.92 93.75,86.92 94,87.17 94.53,87.17 v1(94.55,87.2)
  BOTTOM w0.1: R0418.2 46.35,96.15 v1(46.35,98.45)
PDM_SDI3_M0_ADC: length 106.3
  TOP w0.1: v1(92.7,67.85) 92.7,67.78 92.17,67.25 92.17,63.66 81.69,53.17 72.45,53.17 72.3,53.02 70.95,53.02 v1(70.74,52.81) ; U1301.243 v1(44.55,35.83)
  INNER LAYER 3 w0.1: v1(44.55,35.83) 44.55,36.1 47.35,38.9 47.35,38.9 51.7,43.25 58.44,43.25 60.53,45.34 60.53,47.18 63.98,50.62 68.55,50.62 v1(70.74,52.81) ; J1201.20 115.62,85.92 114.08,85.92 112.62,84.47 112.62,80.62 110.25,78.25 110.25,70.55 109.29,69.59 106.96,69.59 105.41,71.14 101.71,71.14 97.44,66.86 96.31,66.86 95.33,67.85 v1(92.7,67.85)
PHY_CLK125_A: length 3.3
  BOTTOM w0.1: U0902.35 107.33,43.73 108.9,45.3 R0934.1
PHYRSTB_A: length 14.2
  TOP w0.1: v1(109.65,41.05) 108.6,42.1 R0942.2 101.95,42.1 v1(101.72,41.88)
  BOTTOM w0.1: D0905.3 112,39.15 R0948.1 C0903.1 110.44,39.86 110.44,40.26 v1(109.65,41.05) ; U0902.12 102.03,42.12 101.88,41.98 101.83,41.98 v1(101.72,41.88)
REGOUT_A: length 3.7
  BOTTOM w0.2: L0901.1 107,48.08 ; U0902.30 106.47,46.25 107.03,46.8
  BOTTOM w0.3: L0901.1 108.67,48.08 R0988.2
RS232_RXD: length 20.8
  BOTTOM w0.1: U1103.7 108.85,78.05 108.85,76.83 112.92,72.75 112.92,68 113.78,67.15 116.45,67.15 117.85,68.55 117.85,69.92 116.85,70.92 J1201.4
RS232_TXD: length 16.8
  BOTTOM w0.1: U1103.8 109.3,78.05 109.3,76.78 113.2,72.88 113.2,68.05 113.88,67.38 116.33,67.38 116.62,67.67 J1201.2
RS485_A: length 24.9
  BOTTOM w0.1: J1201.8 115.67,73.97 115.67,72.45 116.15,71.97 117.88,71.97 118.53,71.33 118.53,64.86 117.8,64.14 111.29,64.14 110.78,64.65 D1106.1 110.08,64.42 R1123.2 109.05,64.47 108.28,64.47 R1113.2 107.97,64.45 107.69,64.73 U1101.6
RS485_B: length 21.9
  BOTTOM w0.1: J1201.6 116.62,72.67 117.08,72.22 118,72.22 118.72,71.5 118.72,64.78 117.89,63.94 111.29,63.94 110.78,63.42 D1104.1 110.2,63.52 R1123.1 109.05,63.58 R1129.2 108.14,63.47 U1101.7
RTCIC_32KOUT: length 1.2
  BOTTOM w0.1: R1207.1 86.9,69.17 86.58,69.5 U1204.4
RTCIC_INT_L_GPIO0_D3: length 252
  TOP w0.1: v1(97.53,68.72) 97.88,68.38 98.55,68.38 99.12,67.8 99.12,59.9 100.67,58.35 108.85,58.35 113.1,54.1 115.47,54.1 117.2,52.38 117.2,49.55 118.28,48.48 118.28,31.2 115.69,28.61 115.69,26.96 113.9,25.18 113.9,21.6 118.72,16.77 118.72,5.67 115.47,2.42 99.35,2.42 97.85,3.92 81.08,3.92 78.28,6.72 76.97,6.72 v1(76.45,7.25) ; U1301.125 v1(30.55,60.27)
  INNER LAYER 3 w0.1: v1(30.55,60.27) 30.75,60.08 30.75,56.95 30.23,56.42 30.23,51.05 27.07,47.9 24.62,47.9 23.35,46.62 23.35,45.45 26.2,42.6 26.2,32.2 25.3,31.3 25.3,26.43 25.88,25.85 25.88,25 24.62,23.75 24.62,19.07 28.93,14.78 29.73,14.78 32.77,11.72 36.62,11.72 42.23,6.12 57.5,6.12 58.42,7.05 76.25,7.05 v1(76.45,7.25) ; v1(97.53,68.72) 97.42,68.83 90.25,68.83 88.67,67.25 87.27,67.25 87.02,67 83.72,67 v1(83.05,67.67)
  BOTTOM w0.1: U1204.6 R1204.1 v1(83.05,67.67)
SARADC_VIN4: length 94
  TOP w0.1: v1(73.74,55.86) 73.74,56.64 75.53,58.42 81.47,58.42 84.05,61 84.05,63.02 86.03,65 89.67,65 90.15,64.53 v1(90.15,64.47) ; U1301.233 v1(42.05,36.67)
  INNER LAYER 3 w0.1: v1(73.74,55.86) 73.74,55.74 72.5,54.5 69.15,54.5 68.47,53.83 68.47,52.08 68.02,51.62 62.33,51.62 59.44,48.74 59.44,45.71 58,44.26 51.21,44.26 46.32,39.37 46.32,39.37 43.63,36.67 v1(42.05,36.67) ; J1201.3 113.3,70.92 112.53,70.15 112.53,69.61 110.24,67.33 106,67.33 104.45,68.88 102.67,68.88 98.4,64.6 90.28,64.6 v1(90.15,64.47)
SARADC_VIN5: length 101.3
  TOP w0.1: v1(73.03,54.27) 73.25,54.05 81.38,54.05 90.72,63.4 v1(90.72,65.42) ; U1301.228 v1(40.45,36.67)
  INNER LAYER 3 w0.1: v1(90.72,65.42) 91.15,65 98.23,65 102.51,69.28 104.62,69.28 106.17,67.72 110.08,67.72 112.12,69.78 112.12,75.9 113.15,76.92 J1201.9 ; v1(40.45,36.67) 41.48,36.67 41.88,36.27 42.23,36.27 42.42,36.48 43.73,36.48 46.53,39.28 46.53,39.28 51.3,44.05 58.09,44.05 59.65,45.61 59.65,48.65 62.42,51.42 68.12,51.42 68.71,52.01 68.71,53.76 69.22,54.27 v1(73.03,54.27)
SARADC_VIN6: length 100
  TOP w0.1: v1(40.62,37.5) 40.58,37.55 38.35,37.55 38.15,37.35 U1301.223 ; v1(90.2,65.08) 89.95,65.33 86.03,65.33 83.85,63.15 83.85,61.1 81.38,58.62 75.4,58.62 73.08,56.3 v1(73.08,55.83)
  INNER LAYER 3 w0.1: v1(73.08,55.83) 73.08,55.4 72.38,54.7 69.05,54.7 68.28,53.92 68.28,52.2 67.9,51.83 62.12,51.83 59.2,48.9 59.2,45.75 57.93,44.48 51.13,44.48 43.52,36.88 42.42,36.88 42.23,37.08 41.88,37.08 41.67,36.88 40.83,36.88 40.62,37.08 v1(40.62,37.5) ; v1(90.2,65.08) 90.47,64.8 98.32,64.8 102.59,69.08 104.53,69.08 106.08,67.53 110.16,67.53 112.33,69.69 112.33,71.17 114.08,72.92 J1201.5
SARADC_VIN7: length 256
  TOP w0.1: v1(7,86.95) 7,86.53 5.97,85.5 5.97,53.05 1.9,48.98 1.9,43.76 6.5,39.16 6.5,30.7 7.05,30.15 7.05,29.75 v1(6.67,29.38) ; v1(111.58,86.35) 111.47,86.45 109.7,86.45 108.97,87.17 101.2,87.17 100.2,86.17 v1(95.42,86.17) ; v1(111.72,80.75) 113.2,79.28 113.2,76.35 J1201.7 ; U1301.213 v1(34.95,37.52) ; v1(52.83,93.1) 52.55,93.1 51.75,92.3 44.83,92.3 v1(44.62,92.5) ; v1(14.9,94.8) 15.25,94.45 18,94.45 18.32,94.12 v1(19.05,94.12) ; v1(19.62,28.5) 19.62,28.3 19.93,28 19.93,27.75 25.5,22.18 v1(25.9,22.18)
  INNER LAYER 2 w0.1: v1(34.95,37.52) 28.43,37.52 v1(28.38,37.58)
  INNER LAYER 3 w0.1: v1(19.05,94.12) 21.25,96.33 31.75,96.33 v1(32.15,96.72) 32.52,96.35 40.77,96.35 v1(44.62,92.5) ; v1(111.72,80.75) 111.58,80.9 v1(111.58,86.35) ; v1(52.83,93.1) 52.98,93.1 53.33,93.45 53.33,96.58 54.67,97.92 68.14,97.92 70.88,95.19 70.88,86.38 74.48,82.78 77.94,82.78 79.69,84.53 94.25,84.53 94.75,85.03 94.75,85.5 v1(95.42,86.17) ; v1(6.67,29.38) 6.67,28.85 6.95,28.57 7.3,28.57 7.58,28.85 19.27,28.85 v1(19.62,28.5) ; v1(7,86.95) 7.8,87.75 7.8,91.15 8.75,92.1 11.72,92.1 14.43,94.8 v1(14.9,94.8)
  BOTTOM w0.1: v1(25.9,22.18) 26.68,22.95 26.68,25.52 27.4,26.25 27.4,31.05 28.18,31.82 28.18,37.48 28.27,37.58 v1(28.38,37.58) ; R0528.2 31.88,97 v1(32.15,96.72)
SDMMC0_DET_L: length 27.4
  TOP w0.1: U1301.261 49.38,32.85 49.38,31.43 50.62,30.18 54.98,30.18 62.62,22.52 v1(63.98,22.52) ; R0807.1 R0809.2 67.7,19.07 67.33,19.45 66.03,19.45 v1(65.8,19.68)
  INNER LAYER 3 w0.1: v1(65.8,19.68) 65.55,19.43 64.78,19.43 63.98,20.23 v1(63.98,22.52)
SDMMC0_DET_L1: length 2.4
  TOP w0.1: R0807.2 D0808.1 66.8,15.81 J0801.CD
SG368Z_PWRKEY: length 105.9
  TOP w0.1: TP1203.1 v1(101.15,89.9) 101.78,89.9 ; v1(94.47,78.83) 94.4,78.75 94.4,72.28 94.1,71.97 94.1,70.47 91.75,68.12 91.75,63.86 81.54,53.65 v1(71.42,53.65) ; U1301.226 38.15,35.5 38.35,35.7 41.3,35.7 v1(41.45,35.55)
  INNER LAYER 3 w0.1: v1(41.45,35.55) 43.4,35.55 51.5,43.65 58.28,43.65 60.06,45.44 60.06,48.36 62.73,51.02 68.33,51.02 69.15,51.85 69.15,53.2 69.78,53.83 70.8,53.83 70.97,53.65 v1(71.42,53.65) ; v1(101.15,89.9) 101.29,89.76 101.29,81.49 98.7,78.9 94.55,78.9 v1(94.47,78.83)
SPK_OUT_LN: length 4.8
  BOTTOM w0.7: J1001.4 5.28,61.33 6.12,62.17 8.1,62.17
SPK_OUT_LP: length 6.5
  BOTTOM w0.7: J1001.3 5.42,59.33 6.53,60.42 9.65,60.42
SPK_OUT_RN: length 16.2
  BOTTOM w0.55: J1001.1 5.12,55.33 6.12,56.33 13.2,56.33 16.15,59.27 C1025.1 16.82,60.05 B1004.1
SPK_OUT_RP: length 13.5
  BOTTOM w0.55: B1001.1 14.65,60.27 C1023.2 14.65,58.7 12.93,56.98 5.7,56.98 5.35,57.33 J1001.2
SPKN_OUT: length 108.7
  TOP w0.25: v1(3,68.58) D1051.1 J1001.6 ; v1(27.55,72.22) 27.75,72.03 U1301.103
  INNER LAYER 3 w0.2: v1(3,68.58) 2.58,68.58 1.9,67.9 1.9,43.7 6.12,39.48 6.12,31.8 7.98,29.94 20.01,29.94 22.2,32.14 22.2,32.73 23.05,33.58 23.05,41.52 19.95,44.62 19.95,48.52 22.3,50.88 25.79,50.88 27.32,52.41 27.32,72 v1(27.55,72.22)
SPKP_OUT: length 109.4
  TOP w0.25: U1301.104 v1(26.95,72.42) ; J1001.5 2.52,63.33 2.1,63.75 D1050.1 v1(2.7,68.05)
  INNER LAYER 3 w0.2: v1(26.95,72.42) 27,72.38 27,52.52 25.68,51.2 22.2,51.2 19.6,48.6 19.6,44.52 22.7,41.42 22.7,33.65 21.85,32.8 21.85,32.25 19.87,30.27 8.11,30.27 6.42,31.96 6.42,39.63 2.23,43.83 2.23,67.58 v1(2.7,68.05)
TP_INT_L_GPIO0_B5: length 47
  TOP w0.1: J0503.4 41.6,94.95 42.58,93.97 42.58,92.3 v1(42.92,91.95) ; U1301.35 v1(50.95,64.78)
  INNER LAYER 3 w0.1: v1(50.95,64.78) 51.6,65.42 52.83,65.42 54.27,66.88 56.68,66.88 58,68.19 58,71.68 54.68,75 50.03,75 48,77.03 48,86.95 45.8,89.15 45.8,89.7 44.75,90.75 43.6,90.75 42.92,91.42 v1(42.92,91.95)
TP_RST_L_GPIO0_B6: length 46.6
  TOP w0.1: v1(43.38,91.55) 42.75,91.55 42.38,91.92 42.38,92.67 41.88,93.17 D0513.2 41.88,94.22 41.1,95 J0503.3 ; U1301.30 52.55,65.1 v1(52.27,64.83)
  INNER LAYER 3 w0.1: v1(52.27,64.83) 52.55,64.83 54.4,66.67 56.77,66.67 58.2,68.11 58.2,71.77 54.77,75.2 50.12,75.2 48.2,77.12 48.2,87.05 46,89.25 46,89.8 44.85,90.95 43.7,90.95 43.38,91.28 v1(43.38,91.55)
UART4_RX_3.3V: length 10.4
  BOTTOM w0.1: R1160.2 106.1,59.58 106.62,60.1 111.11,60.1 114.43,56.78 J1101.2
UART4_RXD: length 52.9
  TOP w0.1: U1301.349 63.25,54.67 63.62,54.3 63.62,53.38 63.73,53.27 65.05,53.27 65.85,52.48 66.95,52.48 67.42,52.95 68.9,52.95 69.4,53.45 69.4,54.12 74.9,59.62 77.88,59.62 80.35,62.1 v1(80.72,62.1)
  BOTTOM w0.1: R1126.1 103.85,54.35 103.47,53.98 100.42,53.98 99.75,54.65 89.2,54.65 88.17,53.62 87.1,53.62 80.97,59.75 80.97,61.88 80.75,62.1 v1(80.72,62.1)
UART4_RXD_3.3V: length 4.1
  TOP w0.1: v1(105.08,61.55) 105.25,61.38 v1(105.25,59.95)
  BOTTOM w0.1: R1105.1 104.6,61.08 v1(105.08,61.55) ; R1159.1 v1(105.25,59.95)
UART4_TX_3.3V: length 15.1
  BOTTOM w0.1: R1162.2 107.97,58.27 109.05,59.35 111.25,59.35 112.67,57.93 112.67,56.55 113.97,55.25 115.47,55.25 115.67,55.45 115.67,58.08 115.38,58.38 115.18,58.38 J1101.4
UART4_TXD: length 53.4
  TOP w0.1: v1(80.55,61.52) 80.08,61.52 77.97,59.42 75,59.42 69.62,54.05 69.62,53.38 69.15,52.9 69.15,51.8 69.03,51.67 67.65,51.67 67.05,52.27 65.75,52.27 64.95,53.08 U1301.344
  BOTTOM w0.1: v1(80.55,61.52) 80.78,61.3 80.78,59.62 87,53.4 88.38,53.4 89.42,54.45 99.65,54.45 100.35,53.75 103.75,53.75 104.08,54.08 104.5,54.08 104.7,54.27 R1115.2
UART4_TXD_3.3V: length 10.6
  TOP w0.1: v1(106.19,61.41) 107.88,59.73 v1(107.88,59.7)
  BOTTOM w0.1: v1(106.19,61.41) 106.14,61.41 104.38,63.17 104.38,66.2 103.95,66.62 R1111.1 R1117.1 ; R1161.1 v1(107.88,59.7)
UART5_RX_3.3V: length 22
  BOTTOM w0.1: R1156.2 101.83,60 102.17,60.35 103.85,60.35 104.05,60.55 106.15,60.55 106.2,60.5 117.97,60.5 118.5,59.98 118.5,57.91 118.19,57.6 117.99,57.6 J1101.1
UART5_RXD: length 38.1
  TOP w0.1: v1(89.58,55.7) 89.58,55.3 83.65,49.38 70.45,49.38 69.05,47.97 69.05,47.58 68.95,47.48 U1301.331
  BOTTOM w0.1: v1(89.58,55.7) 89.83,55.45 100.4,55.45 101.25,54.6 R1130.1
UART5_RXD_3.3V: length 13.4
  TOP w0.1: v1(107.22,70.2) 107.22,69.95 103.33,66.05 103.33,60.33 v1(102.95,59.95)
  BOTTOM w0.1: R1155.1 102.67,59.67 v1(102.95,59.95) ; R1133.2 v1(107.22,70.2)
UART5_TX_3.3V: length 13.8
  BOTTOM w0.1: R1158.2 104.4,59.67 105.08,60.35 106.03,60.35 106.08,60.3 116,60.3 116.22,60.07 116.22,59.87 J1101.3
UART5_TXD: length 40.6
  TOP w0.1: v1(89.05,55.4) 89.05,55.08 83.55,49.58 70.25,49.58 68.95,48.27 U1301.332
  BOTTOM w0.1: v1(89.05,55.4) 89.2,55.25 100.3,55.25 101.38,54.17 102.9,54.17 103,54.27 R1119.1
UART5_TXD_3.3V: length 14.2
  TOP w0.1: v1(107.22,71.05) 107.62,70.65 107.62,70.03 103.55,65.95 v1(103.55,59.95)
  BOTTOM w0.1: R1157.1 v1(103.55,59.95) ; R1120.2 v1(107.22,71.05)
UART7_RXD: length 29.8
  TOP w0.1: v1(75.3,55.1) 75.3,55.15 75.38,55.23 75.38,55.45 77.03,57.1 81.35,57.1 84.2,59.95 v1(85.28,59.95) ; U1301.328 v1(66.33,47.48)
  INNER LAYER 3 w0.1: v1(75.3,55.1) 75.28,55.08 75.28,49.9 73.75,48.38 70.7,48.38 70.03,47.7 66.6,47.7 66.38,47.48 v1(66.33,47.48)
  BOTTOM w0.1: R0720.1 v1(85.28,59.95)
UART7_TXD: length 29.3
  TOP w0.1: v1(75.78,54.73) 75.72,54.77 75.72,55.45 77.17,56.9 81.55,56.9 82.85,58.2 v1(84.22,58.2) ; U1301.327 v1(65.6,46.67)
  INNER LAYER 3 w0.1: v1(75.78,54.73) 75.47,54.42 75.47,49.77 73.88,48.17 70.8,48.17 70.12,47.5 66.92,47.5 66.5,47.08 65.9,47.08 65.6,46.77 v1(65.6,46.67)
  BOTTOM w0.1: v1(84.22,58.2) R0713.1
UART8_RXD: length 73.1
  TOP w0.1: U1301.357 69.08,56.27 69.3,56.5 69.3,57.42 73.17,61.3 75.22,61.3 79.97,66.05 83.8,66.05 86.07,68.32 89.02,68.32 92.81,72.11 92.81,83.85 92.95,83.99 92.95,86.72 94.1,87.88 109.3,87.88 109.7,87.47 113.8,87.47 114.15,87.83 115.53,87.83 J1201.22
UART8_TXD: length 72
  TOP w0.1: U1301.361 68.65,57.08 73.08,61.5 75.12,61.5 79.9,66.28 83.67,66.28 85.94,68.54 88.94,68.54 92.6,72.2 92.6,83.97 92.75,84.12 92.75,86.85 93.97,88.08 109.47,88.08 109.85,87.7 113.72,87.7 114.05,88.03 115.25,88.03 115.62,88.4 115.62,89.92 J1201.24
USB3_OTG0_ID: length 186.5
  TOP w0.1: v1(59.62,2.27) 57.08,4.83 41.98,4.83 38.95,7.85 v1(38.88,7.85) 39,7.72 R0325.2 ; U1301.118 v1(29.7,63.48) ; v1(102.69,3.26) 102.79,3.26 103.17,2.88 115.22,2.88 118.15,5.8 118.15,16.75 113.47,21.43 113.47,25.38 114.53,26.43 114.53,30.88 114.88,31.23 S0301.2
  INNER LAYER 3 w0.1: v1(29.7,63.48) 29.6,63.48 29.45,63.33 29.45,51.42 26.8,48.77 23.15,48.77 22.2,47.83 22.2,45.25 25.23,42.23 25.23,32.7 24.2,31.68 24.2,18.9 28.73,14.38 29.5,14.38 32.55,11.32 36.42,11.32 38.88,8.88 v1(38.88,7.85) ; v1(102.69,3.26) 102.25,2.83 80.17,2.83 79.83,3.17 60.35,3.17 59.62,2.45 v1(59.62,2.27)
USB3_OTG0_VBUSDET: length 69.7
  TOP w0.1: U1301.111 29.43,66.67 v1(29.45,66.7)
  TOP w0.25: R0312.2 32.48,11 32.12,11.35 v1(31.6,11.35)
  TOP w0.5: 32.48,9.88 R0312.2
  INNER LAYER 3 w0.1: v1(31.6,11.35) 31.6,11.97 29.43,14.15 28.65,14.15 24,18.8 24,31.77 25.02,32.8 25.02,42.13 21.98,45.17 21.98,47.91 23.05,48.98 26.68,48.98 29.25,51.55 29.25,66.53 29.43,66.7 v1(29.45,66.7)
USB_HOST_PWREN_H_GPIO0_A6: length 123.2
  TOP w0.1: v1(42.3,62.4) 40.95,62.4 39.45,63.9 37.88,63.9 36.83,64.95 35.17,64.95 34.95,65.17 U1301.85 ; v1(43.23,31.77) 43.23,31.27 44.98,29.52 44.98,26.75 ; 44.85,26.62 44.98,26.62 ; 44.85,26.62 44.98,26.75 ; 44.85,26.62 40.12,26.62 38.48,24.98 v1(37.95,24.98) ; 44.98,26.62 45.1,26.62 ; 44.98,26.62 44.98,26.75 ; v1(66.08,27.9) 66.38,28.2 73.42,28.2 73.65,27.98 v1(73.65,27.2) ; 45.1,26.62 44.98,26.75 ; 45.1,26.62 53.05,26.62 59.14,20.53 59.14,20.39 v1(58.85,20.1) ; v1(55.15,41.75) 55.15,45.02 v1(54.95,45.23)
  INNER LAYER 3 w0.1: v1(55.15,41.75) 54.85,41.45 51.98,41.45 51.45,40.92 51.45,36.92 51.13,36.6 48.21,36.6 46.63,35.02 42.75,35.02 42.17,34.45 42.17,33.33 43.23,32.27 v1(43.23,31.77) ; v1(42.3,62.4) 48.95,62.4 54.9,56.45 v1(54.9,54.85) ; v1(66.08,27.9) 66.08,26.68 64.88,25.48 64.7,25.48 60.56,21.34 60.16,21.34 58.92,20.1 v1(58.85,20.1)
  BOTTOM w0.1: U0601.4 R0607.2 R0602.2 74.83,27 74.62,27.2 v1(73.65,27.2) ; v1(66.08,27.9) 66.08,27.7 66.83,26.95 R0612.2 68.08,26.98 R0618.2 69.28,27.8 ; v1(37.95,24.98) 38.48,24.45 38.48,23.88 38.05,23.88 37.73,24.2 R0624.2 R0623.2 ; v1(54.9,54.85) 54.95,54.8 v1(54.95,45.23)
USB_VBUS: length 25.4
  TOP w0.4: J0302.1 34.98,5.54
  TOP w0.5: C0352.1 33.76,6.37 33.76,6.99 C0353.1 33.33,7.58 33.32,7.59 33.32,8.54 D0354.1 33.32,8.56 33.32,9.82 R0302.1 33.38,11 34.1,11.72 ; 34.1,5.85 34.52,5.85 ; D0355.1 40.34,11.74 40.33,11.72 C0355.1 C0354.1 ; J0301.1 45.13,11.02 44.58,11.57 41.4,11.57 41.3,11.68
  TOP w0.9: 34.84,12.13 35.74,11.22 C0354.1
  INNER LAYER 2 w0.4: J0301.1 45.13,11.02 44.67,11.47 41.58,11.47 v1(41.25,11.8)
  vias: v1(34.3,14.15) v1(34.9,14.15)
V_RTC: length 12.6
  BOTTOM w0.1: U1204.10 83.3,71.75 C1201.2 R1301.2
  BOTTOM w0.2: R1301.2 80.2,72.05 77.15,75.1 BAT1201.1
V_UP/BOOT: length 89.9
  TOP w0.1: S1201.2 D1202.1 113.78,39.4 TP1201.1 111.67,38.65 111.25,38.23 103.53,38.23 102.22,39.52 98.35,39.52 96.38,37.55 v1(96.03,37.55) ; U1301.236 41.35,33.52 41.62,33.8 v1(43.1,33.8) ; v1(74.35,46.27) 74.7,45.92 75.6,45.92 76.05,45.48 83.67,45.48 v1(83.85,45.65)
  INNER LAYER 3 w0.1: v1(43.1,33.8) 47.65,33.8 48.9,35.05 53.6,35.05 55.42,33.23 56.15,33.23 56.41,33.49 56.41,35.49 56.77,35.85 59.12,35.85 60.1,36.83 60.1,37.96 61.39,39.25 62.83,39.25 68.7,45.12 71.28,45.12 71.75,45.6 71.75,45.88 72.82,46.95 73.67,46.95 v1(74.35,46.27) ; v1(83.85,45.65) 83.76,45.56 83.76,45.42 91.42,37.75 95.45,37.75 95.65,37.55 v1(96.03,37.55)
VDC_3V3: length 433.6
  TOP w0.2: v1(101.12,60.15) 102.25,59.02 110.4,59.02 110.8,59.42 ; v1(111.27,58.15) v1(110.77,58.15)
  TOP w0.3: R0505.1 19.15,49.33 17.48,47.65 17.48,44.42 v1(16.02,42.98) ; v1(108.85,61.83) 108.92,61.9 110.8,61.9
  TOP w0.5: v1(118.4,50.15) 118.62,50.38 118.62,63.62 117.4,64.85 v1(112.05,64.85) 111.5,64.85 110.8,65.55
  TOP w0.6: 17.1,31.45 17.1,27.88 18.4,26.57
  TOP w0.7: 68.35,88.85 68.35,90.7 69.3,91.65 L0401.1 ; C0402.2 v1(67.55,88.7)
  TOP w1: 117.58,2.42 116.9,1.75 99.08,1.75 97.58,3.25 80.83,3.25 79.08,5 78.25,5 ; v1(105.38,51.83) 105.38,48.5 98.92,42.05 96.17,42.05 95.95,41.83 94.97,41.83 93.85,40.7
  TOP w2: 110.8,59.42 110.8,61.9
  TOP w3: 108.25,73.33 110.8,70.78 110.8,61.9
  INNER LAYER 2 w0.5: v1(112.05,64.85) 117.42,64.85 118.6,63.67 118.6,50.35 v1(118.4,50.15)
  INNER LAYER 3 w0.3: v1(17.45,31.8) 17.45,34.77 14.8,37.42 14.8,41.75 v1(16.02,42.98)
  INNER LAYER 3 w0.6: 17.99,26.44 17.25,25.7 v1(17.25,17.68)
  INNER LAYER 3 w0.7: v1(61.25,89.47) 61.25,89.12 63.5,86.88 66.55,86.88 67.55,87.88 v1(67.55,88.7)
  INNER LAYER 3 w0.8: v1(77.95,5.1) 59.55,5.1 57.25,2.8 42.65,2.8 40.42,5.03 32.7,5.03 31.27,6.45 16.65,6.45 14.8,8.3 14.8,11.72 17.25,14.18 v1(17.25,17.18) v1(17.25,17.68)
  INNER LAYER 3 w1: v1(110.77,58.15) 105.4,52.77 105.4,52.15 ; v1(117.83,2.67) 118.55,3.4 118.55,16.43 113.53,21.45 113.53,25.27 118.4,30.15 v1(118.4,49.65)
  INNER LAYER 3 w3: v1(101.58,73.35) 93.63,73.35 89.45,77.53 64.88,77.53 61.4,81
  BOTTOM w0.1: R0105.1 49.6,84.85 49.3,85.15 49.3,90.58 49.55,90.83 57.52,90.83 C0109.2 ; R1103.2 101.1,60.17 v1(101.12,60.15)
  BOTTOM w0.15: v1(101.12,60.15) 101.15,60.12 101.15,57.35 C1110.2 C1102.1 102.35,57.25 102.72,56.88 U1102.A2
  BOTTOM w0.2: R1113.1 107.9,65.35 107.75,65.5 106.25,65.5 105.65,64.9 105.65,62.77 106.23,62.2 107.05,62.2 ; v1(102.08,73.35) 103.08,72.35 C1101.2 U1103.16 ; v1(17.25,17.18) 17.05,16.98 D0401.2 ; R1210.1 82.12,66.9 82.53,66.5 86.22,66.5 87.2,67.47 87.2,68.28 88.1,68.28 90.22,70.4 98.13,70.4 v1(101.58,73.85)
  BOTTOM w0.3: v1(108.85,61.83) C1106.2 108.03,61.83 107.66,62.2 107.05,62.2 ; v1(17.45,31.8) C0517.2 R0529.1
  BOTTOM w0.5: 62.98,91.83 R0427.2 61.67,91.83 C0409.1 ; C0405.2 R0407.1 63,91.4
  BOTTOM w0.6: v1(17.45,31.8) 17.43,31.82 12.68,31.82 C0521.1 12.22,32.3 12.2,32.33 R0525.1 13.5,33.35 Q0501.2
  BOTTOM w0.9: TP0103.1 57.9,91.33
  vias: v1(16.95,31.8) v1(18.07,26.52) v1(18.57,26.52) v1(60.23,82.03) v1(60.23,81.53) v1(60.3,89.72) v1(60.3,89.22) v1(60.73,82.03) v1(60.73,81.53) v1(60.8,89.72) v1(60.8,89.22) v1(61.23,82.05) v1(61.23,81.55) v1(78.45,5.1) v1(93.2,40.88) v1(93.58,40.52) v1(102.08,73.85) v1(105.38,52.33) v1(117.47,2.27)
VDC_5V: length 69.6
  TOP w0.6: v1(21.85,29.45) 22.98,28.32 v1(26.37,28.32)
  BOTTOM w0.1: C0104.2 34.5,55.02 34.02,55.02 33.9,55.15 33.9,56.05 33.2,56.05 32.02,57.23 32.02,68.6 32.3,68.88 34.05,68.88 34.77,68.15 R0102.1
  BOTTOM w0.6: v1(21.85,29.45) 21.85,28.7 20.57,27.43 10.8,27.43 9.04,25.66 ; v1(26.37,28.32) 26.37,31.27 27.3,32.2 27.3,38.5 27.7,38.9 27.7,45.42 28.18,45.9
  BOTTOM w1.5: 28.18,45.9 32.83,50.55 TP0101.1 32.8,54.45 32.8,54.48 34.33,56
XTAL1A: length 5.5
  BOTTOM w0.1: U0902.36 108.5,43.33 108.67,43.5 R0936.2 C0921.2 110.28,43.05 111.33,43.05 X0901.1
XTAL2A: length 5.3
  BOTTOM w0.1: U0902.37 108.45,42.92 108.78,42.6 R0936.1 109.03,42.65 C0912.2 110.53,42.65 X0901.3 R0925.1
N15679654: length 2.1
  BOTTOM w0.3: C0919.1 98.65,35.25 98.92,34.98 98.92,33.77 U0901.1
N15679880: length 9.5
  BOTTOM w0.3: 110.28,36.08 110.28,35.65 110.85,35.08 110.85,32.17 110.1,31.43 108.3,31.43 107.92,31.8 107.92,33.67 U0901.10
N15679892: length 13.5
  BOTTOM w0.3: U0901.7 104.92,33.7 104.92,31.93 106.38,30.48 109.75,30.48 111.25,31.98 111.25,35.4 111.12,35.52 111.12,36.08
N15679900: length 8.6
  BOTTOM w0.3: U0901.4 101.95,32.77 101.4,32.23 98.3,32.23 97.65,32.88 C0988.1
N15680148: length 4.1
  TOP w0.1: J0901.10 110.42,17.02 R0939.2 R0908.1
N15680216: length 20.6
  TOP w0.3: v1(102.6,21.77) 100.62,19.8 v1(99.6,19.8) ; v1(105.55,21.77) v1(108.55,21.77) 109.65,22.88 C0909.2
  INNER LAYER 2 w0.3: v1(108.55,21.77) 106.78,20 103.97,20 102.6,21.38 v1(102.6,21.77)
  BOTTOM w0.3: R0918.1 v1(102.6,21.77) ; v1(99.6,19.8) 98.92,20.48 R0911.1 ; v1(108.55,21.77) R0924.1 ; R0943.1 v1(105.55,21.77)
N15680388: length 4.9
  TOP w0.1: R0933.2 R0922.1 113.08,17.32 D0901.1 113.1,16.63 J0901.9
N15680410: length 4.7
  TOP w0.1: J0901.12 101.09,14.94 102.65,16.5 103.12,16.5 103.6,16.98 R0938.2 R0951.2
N15680444: length 5.1
  TOP w0.1: R0930.2 105.35,19.15 R0927.2 D0903.1 105.35,16.89 J0901.11
